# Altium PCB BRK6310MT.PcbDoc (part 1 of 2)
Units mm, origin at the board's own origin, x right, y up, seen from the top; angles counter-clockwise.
Board outline 165 x 90 mm, 4 copper layers (L1-Top, L2-Plane-1, L3-Plane-2, L4-Bottom), stack 1.539 mm thick; 47 components, 158 nets, 545 pads, 116 vias.
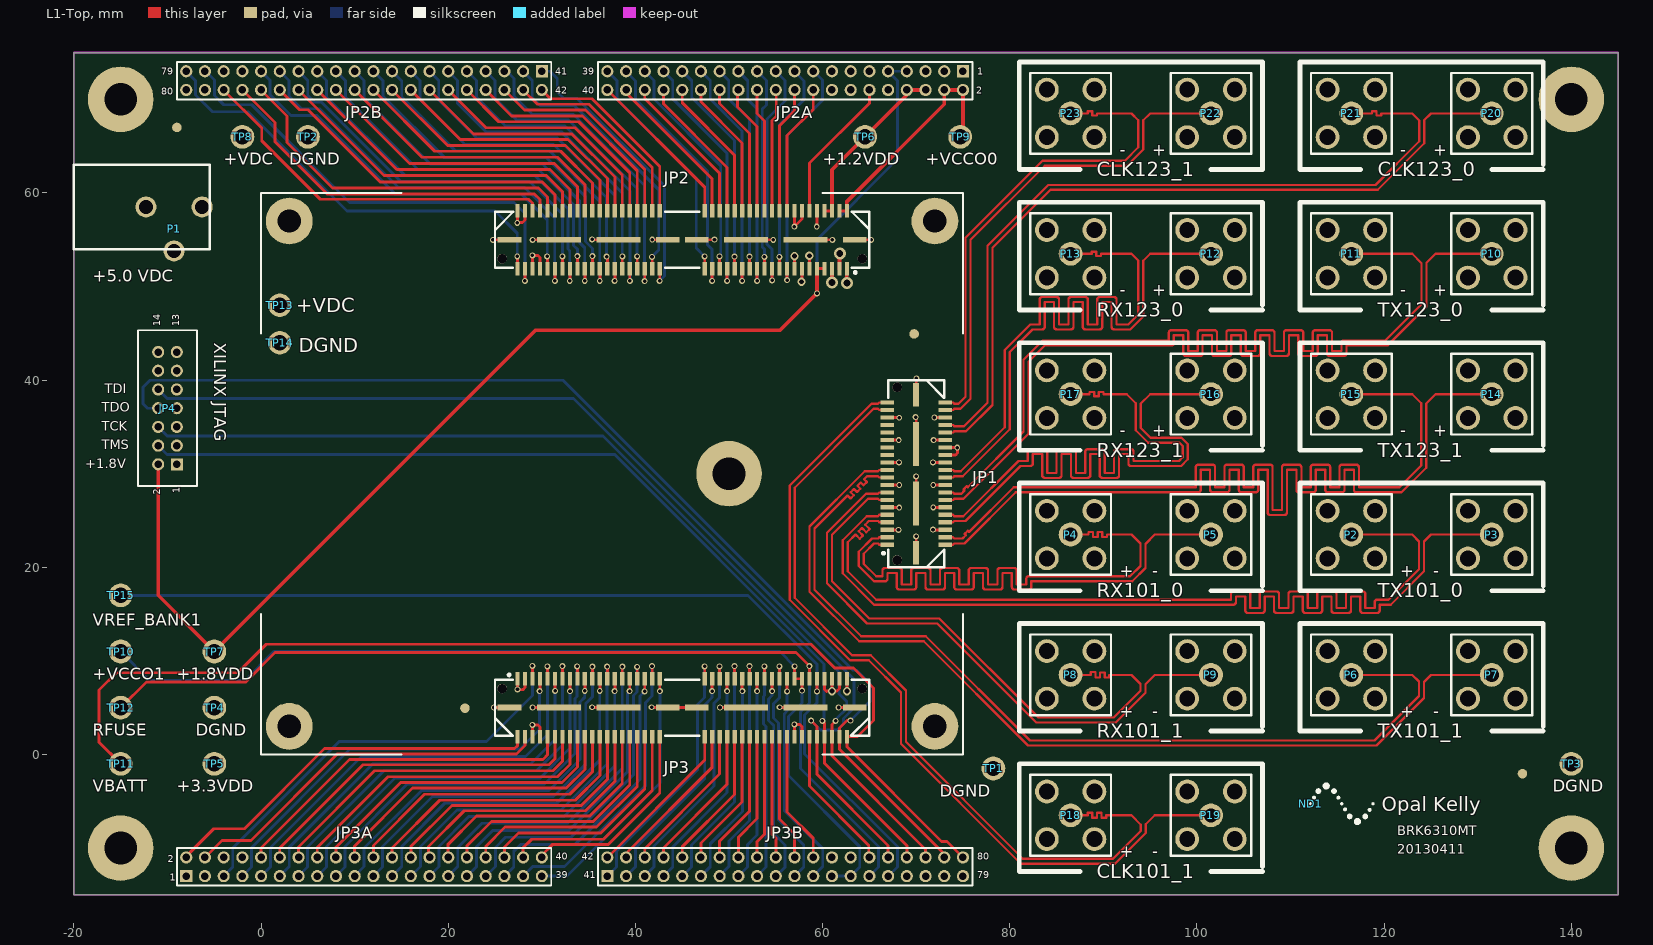
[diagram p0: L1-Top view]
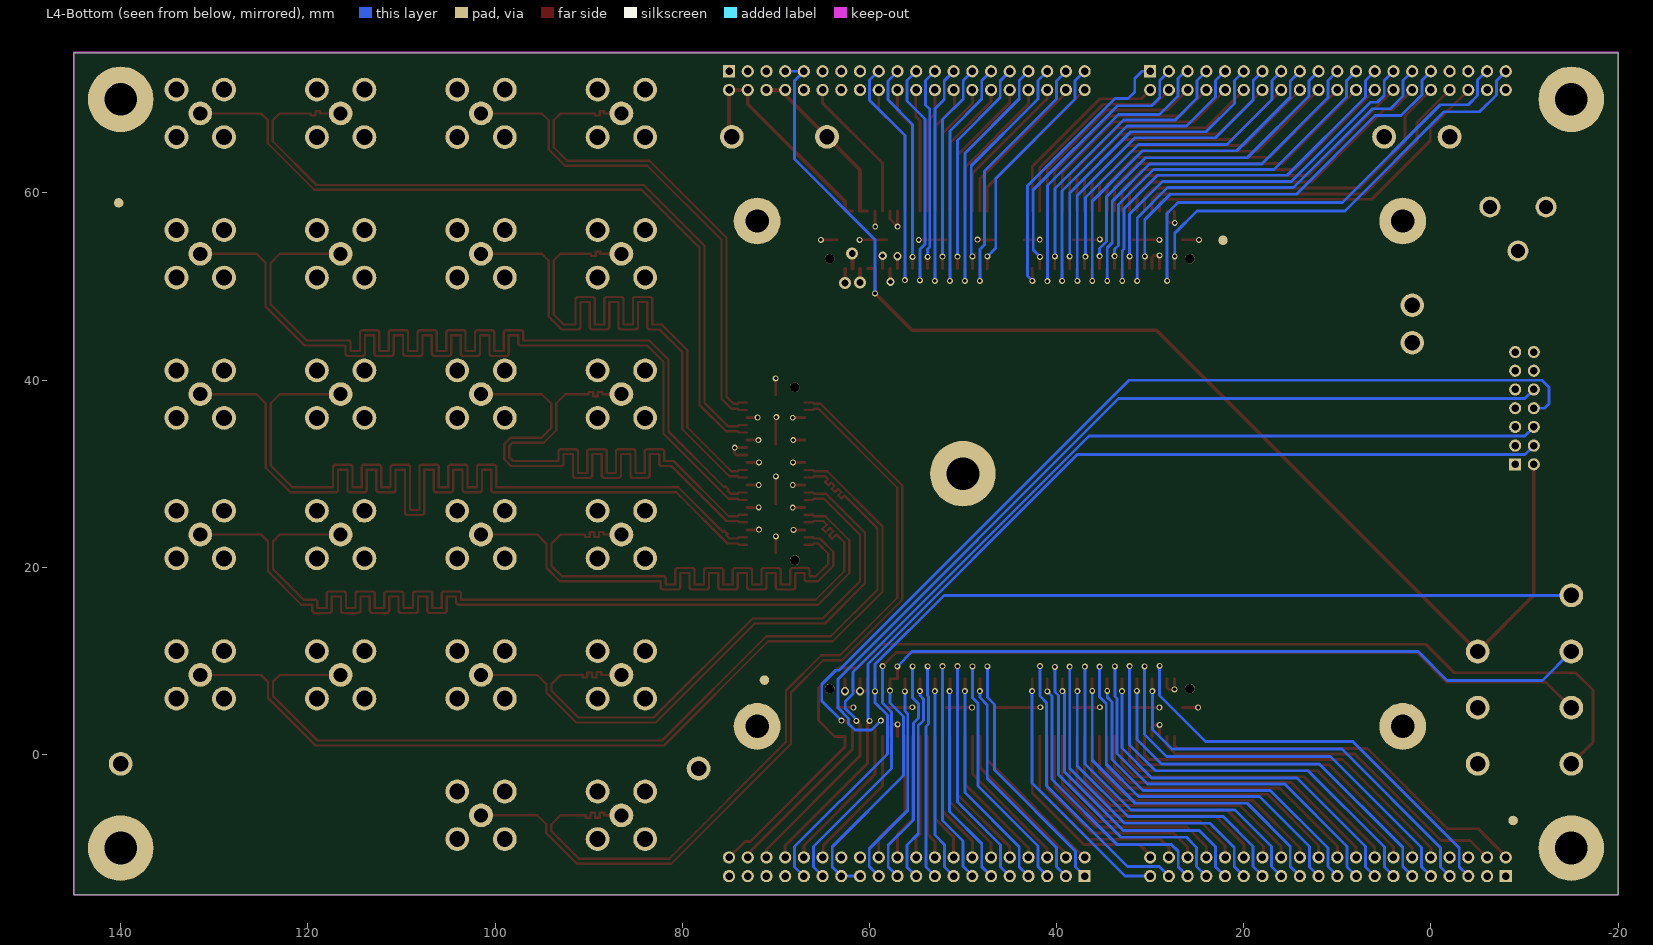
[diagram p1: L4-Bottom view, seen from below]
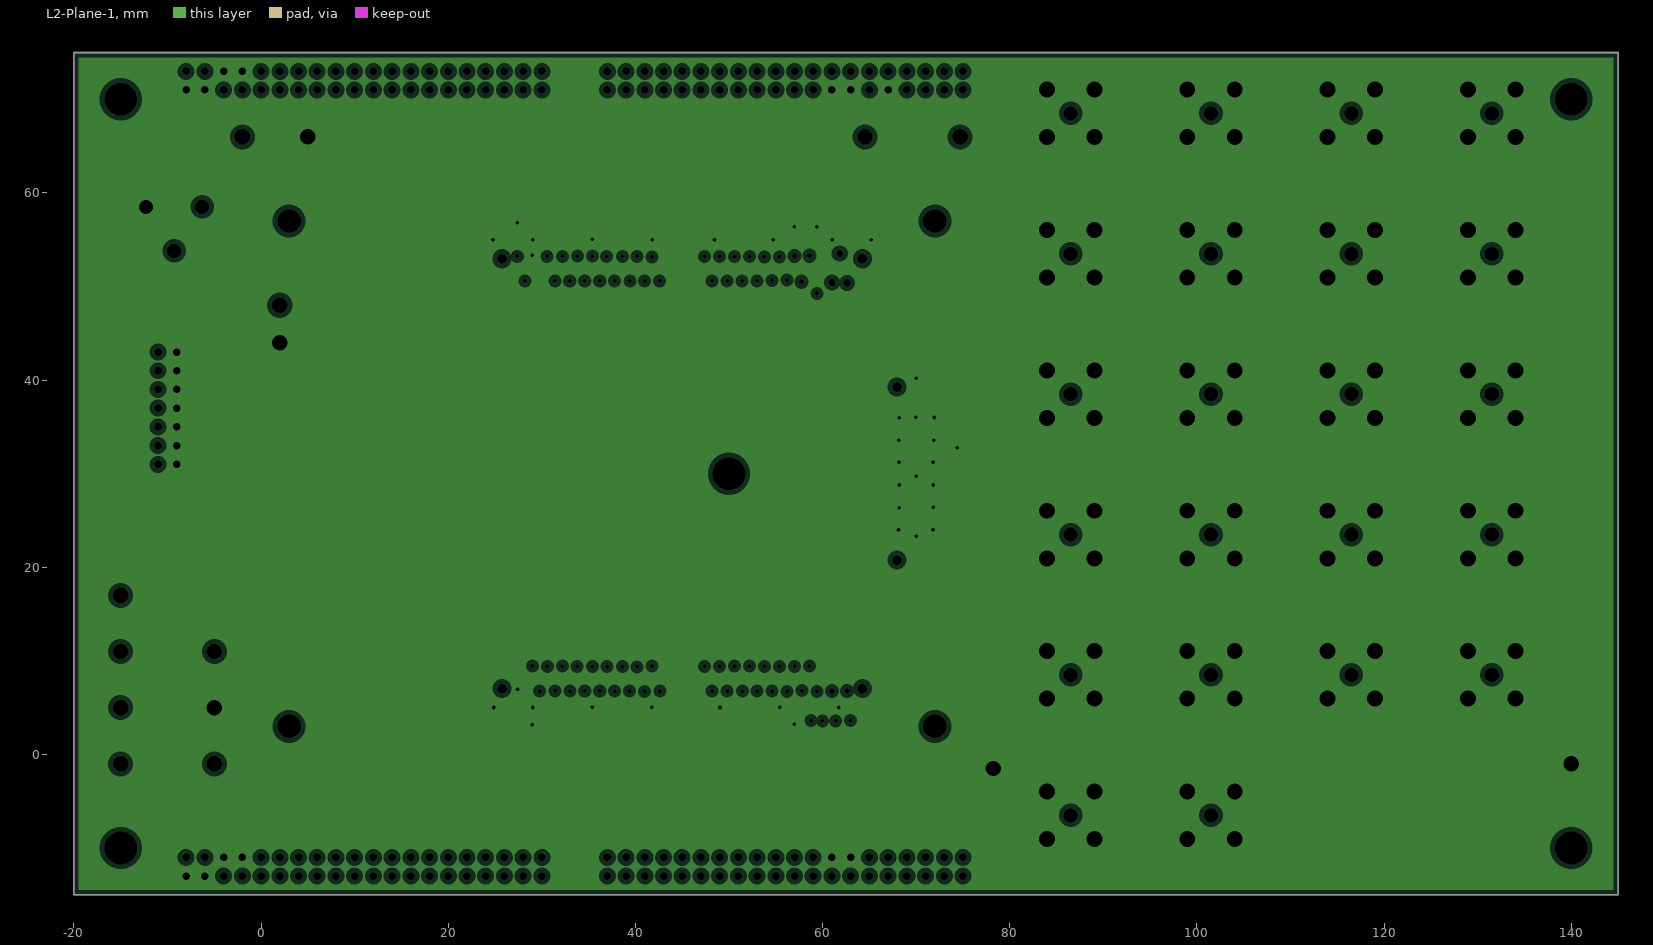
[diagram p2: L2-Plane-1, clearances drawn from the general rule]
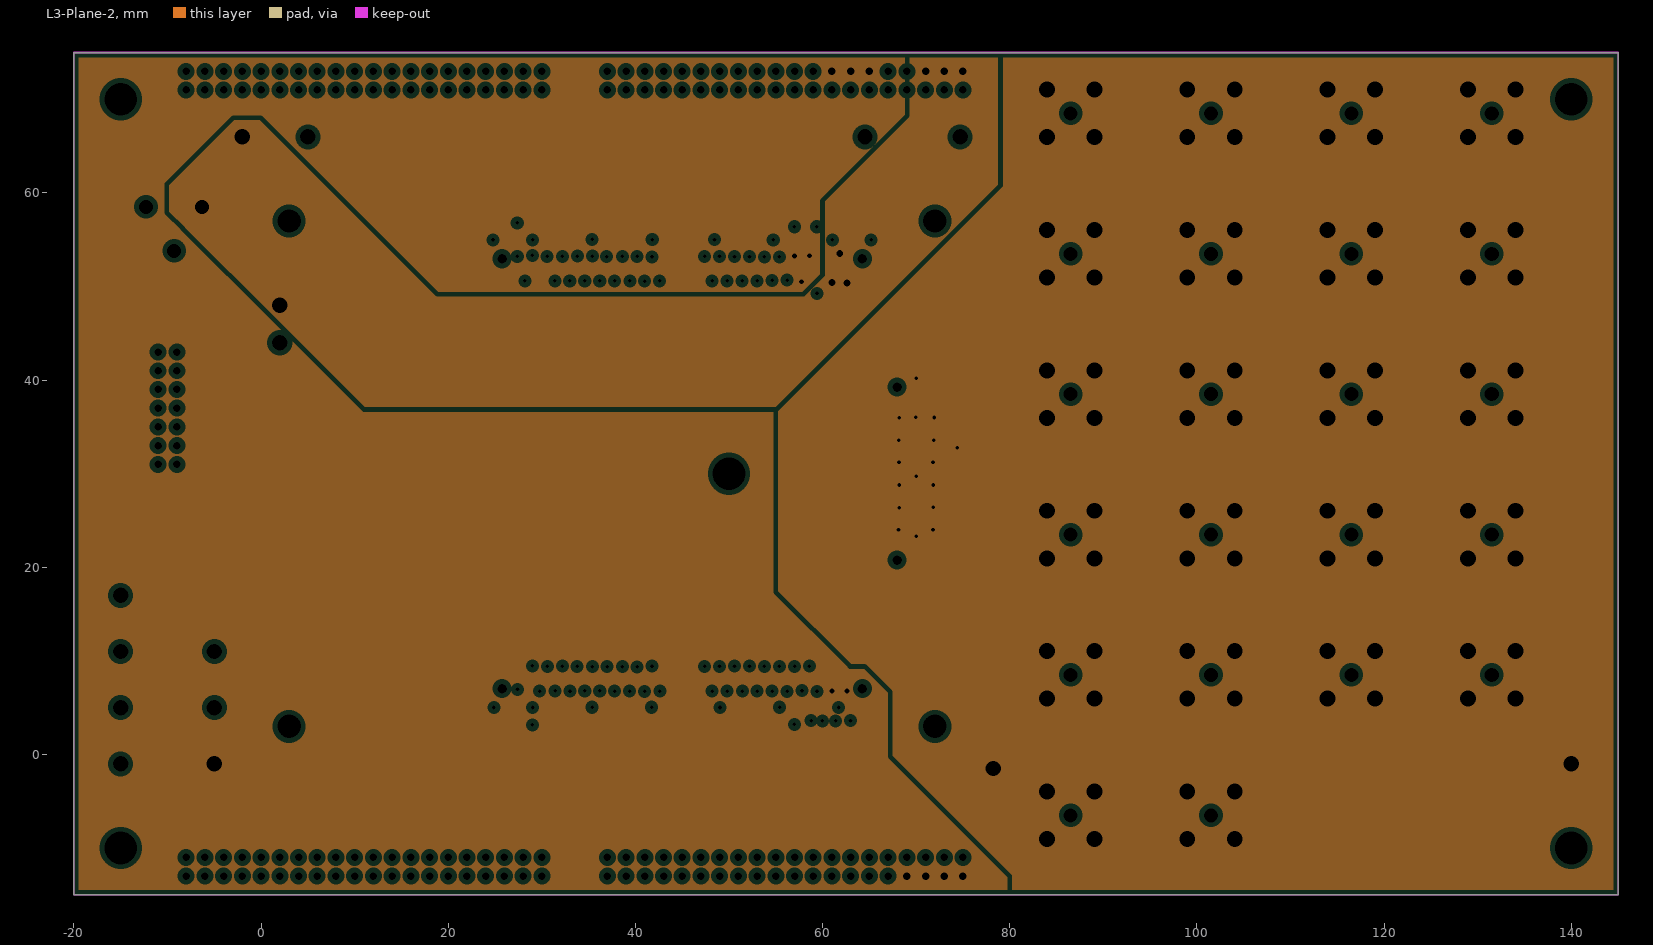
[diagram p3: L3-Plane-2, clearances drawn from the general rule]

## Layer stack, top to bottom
L1-Top: signal copper 0.0533
Dielectric: prepreg 0.1854, FR-4, Dk 4.8
L2-Plane-1: plane copper 0.0356, net DGND
Dielectric: core 0.9906, FR-4, Dk 4.8
L3-Plane-2: plane copper 0.0356, net (Multiple Nets)
Dielectric: prepreg 0.1854, FR-4, Dk 4.8
L4-Bottom: signal copper 0.0533

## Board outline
-20,-15 -20,75 145,75 145,-15

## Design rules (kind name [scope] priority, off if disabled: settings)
Clearance [All] p1: gap=0.152
DiffPairsRouting okxDiffRouting100ohm [All] p1: maxlimit=0.292 minlimit=0.292 mostfreqgap=0.292 maxuncoupledlength=12.7 // Differential pair spacing for all 100ohm diff routes based on Saturn Stackup.
FabricationTestPointUsage TestPointUsage [All] p1: valid=0 allowmultiple=FALSE
FabricationTestpoint Testpoint [All] p1: side=3 testpointundercomponent=TRUE minsize=1.016 maxsize=2.54 preferedsize=1.524 minholesize=0 maxholesize=1.016 preferedholesize=0.813 testpointgrid=0.025 allowsidetop=TRUE allowsidebottom=TRUE usegrid=TRUE gridtolerance=0
HoleSize [All] p1: absolutevalues=TRUE maxlimit=6 minlimit=0.381 maxpercent=80.000 minpercent=20.000
MatchedLengths okMatchedMGTDiffPairs [InNetClass('okMGT')] p1: tolerance=0.152 checknetsindiffpair=TRUE checkdiffpairvsdiffpair=FALSE checkothers=FALSE // Control skew within MGTdiferential pairs.
MatchedLengths okMatchedMGTRefClkDiffPairs [InNetClass('okMGTRefClk')] p2: tolerance=1.676 checknetsindiffpair=TRUE checkdiffpairvsdiffpair=FALSE checkothers=FALSE // Control skew within MGTREFCLKdiferential pairs.
MatchedLengths okMatchedMGTTX [InDifferentialPairClass('okMGTDiffTXMatch')] p3: tolerance=4.699 checknetsindiffpair=TRUE checkdiffpairvsdiffpair=TRUE checkothers=TRUE // MGT TX matched to 31.25ps
MatchedLengths okMatchedMGTRX [InDifferentialPairClass('okMGTDiffRXMatch')] p4: tolerance=4.699 checknetsindiffpair=TRUE checkdiffpairvsdiffpair=TRUE checkothers=TRUE // MGT RX matched to 31.25ps
PlaneClearance [All] p1: clearance=0.508
PlaneConnect [All] p1: planeconnectstyle=Relief reliefexpansion=0.508 reliefentries=4 reliefconductorwidth=0.254 reliefairgap=0.254
PolygonConnect "Via Connect" [IsVia] p1: connectstyle=Direct reliefconductorwidth=0.254 reliefentries=4 polygonreliefangle="90 Angle" airgapwidth=0.254
PolygonConnect [All] p2: connectstyle=Relief reliefconductorwidth=0.254 reliefentries=4 polygonreliefangle="90 Angle" airgapwidth=0.254
RoutingVias [All] p1: holewidth=0.381 width=0.635 viastyle="Through Hole" minholewidth=0.254 minwidth=0.508 maxholewidth=1.27 maxwidth=2.54
SilkscreenOverComponentPads [All] p1: minsilkscreentomaskgap=0.254
SolderMaskExpansion [All] p1: expansion=0.102
Width okxWidthDiff100ohm [(InDifferentialPairClass('All Differential Pairs'))] p1: maxlimit=0.241 minlimit=0.241 preferedwidth=0.241 minimp=50.000000 maximp=50.000000 favimp=50.000000 // 100 ohm differential pair routing based on 4 layer stackup from Saturn
Width okWidth50ohm [All] p2: maxlimit=1.016 minlimit=0.305 preferedwidth=0.305 minimp=50.000000 maximp=50.000000 favimp=50.000000 // 50 ohm SE routing based on 4 layer stackup from Saturn
21 further rules are at their usual default settings.

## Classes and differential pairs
net class okMGT: RX101_0N RX101_0P RX101_1N RX101_1P RX123_0N RX123_0P RX123_1N RX123_1P TX101_0N TX101_0P TX101_1N TX101_1P TX123_0N TX123_0P TX123_1N TX123_1P
differential pair class okMGTDiffPairs: D_CLK101_1 D_CLK123_0 D_CLK123_1 D_RX101_0 D_RX101_1 D_RX123_0 D_RX123_1 D_TX101_0 D_TX101_1 D_TX123_0 D_TX123_1
differential pair class okMGTDiffTXMatch: D_TX101_0 D_TX101_1 D_TX123_0 D_TX123_1
differential pair class okMGTDiffRXMatch: D_RX101_0 D_RX101_1 D_RX123_0 D_RX123_1
net class okMGTRefClk: CLK101_1N CLK101_1P CLK123_0N CLK123_0P CLK123_1N CLK123_1P
differential pair D_TX123_1: +TX123_1P -TX123_1N
differential pair D_TX123_0: +TX123_0P -TX123_0N
differential pair D_RX123_1: +RX123_1P -RX123_1N
differential pair D_RX123_0: +RX123_0P -RX123_0N
differential pair D_CLK123_0: +CLK123_0P -CLK123_0N
differential pair D_TX101_1: +TX101_1P -TX101_1N
differential pair D_TX101_0: +TX101_0P -TX101_0N
differential pair D_RX101_1: +RX101_1P -RX101_1N
differential pair D_RX101_0: +RX101_0P -RX101_0N
differential pair D_CLK123_1: +CLK123_1P -CLK123_1N
differential pair D_CLK101_1: +CLK101_1P -CLK101_1N

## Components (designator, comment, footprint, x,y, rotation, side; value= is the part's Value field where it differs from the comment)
JP1 "QTE-020-01-F-D-A" QTE-020-01-X-D-A 70,30 r90 top locked
JP2 "QTE-040-01-F-D-A" QTE-040-01-X-D-A 45,55 r180 top locked
JP2A "Header 20X2" HDR2X20-2MM 56,72 r180 top
JP2B "Header 20X2" HDR2X20-2MM 11,72 r180 top
JP3 "QTE-040-01-F-D-A" QTE-040-01-X-D-A 45,5 r0 top locked
JP3A "Header 20X2" HDR2X20-2MM 11,-12 r0 top
JP3B "Header 20X2" HDR2X20-2MM 56,-12 r0 top
JP4 "JTAG" XILINX-JTAG -10,37 r90 top
ND1 "OKLOGO" oklogotiny 112.145,-5.268 r0 top
P1 "+5.0 VDC" CUI-PJ102A -20,58.5 r270 top
P2 "TX101_0" SMA 116.5,23.5 r0 top
P3 "TX101_0N" SMA 131.5,23.5 r0 top
P4 "RX101_0" SMA 86.5,23.5 r0 top
P5 "RX101_0N" SMA 101.5,23.5 r0 top
P6 "TX101_1" SMA 116.5,8.5 r0 top
P7 "TX101_1N" SMA 131.5,8.5 r0 top
P8 "RX101_1" SMA 86.5,8.5 r0 top
P9 "RX101_1N" SMA 101.5,8.5 r0 top
P10 "TX123_0P" SMA 131.5,53.5 r0 top
P11 "TX123_0" SMA 116.5,53.5 r0 top
P12 "RX123_0P" SMA 101.5,53.5 r0 top
P13 "RX123_0" SMA 86.5,53.5 r0 top
P14 "TX123_1P" SMA 131.5,38.5 r0 top
P15 "TX123_1" SMA 116.5,38.5 r0 top
P16 "RX123_1P" SMA 101.5,38.5 r0 top
P17 "RX123_1" SMA 86.5,38.5 r0 top
P18 "CLK101_1" SMA 86.5,-6.5 r0 top
P19 "CLK101_1N" SMA 101.5,-6.5 r0 top
P20 "CLK123_0P" SMA 131.5,68.5 r0 top
P21 "CLK123_0" SMA 116.5,68.5 r0 top
P22 "CLK123_1P" SMA 101.5,68.5 r0 top
P23 "CLK123_1" SMA 86.5,68.5 r0 top
TP1 "DGND" TP_MED#1 78.25,-1.5 r0 top
TP2 "DGND" TP_MED#1 5,66 r0 top
TP3 "DGND" TP_MED#1 140,-1 r180 top
TP4 "DGND" TP_MED#1 -5,5 r0 top
TP5 "+3.3VDD" TP_MED#1 -5,-1 r0 top
TP6 "+1.2VDD" TP_MED#2 60,66 r0 top
TP7 "+1.8VDD" TP_MED#1 -5,11 r0 top
TP8 "+VDC" TP_MED#1 -2,66 r0 top
TP9 "+VCCO0" TP_MED#3 75,66 r0 top
TP10 "+VCCO1" TP_MED#4 -15.8,11 r0 top
TP11 "VBATT" TP_MED#1 -15,-1 r0 top
TP12 "RFUSE" TP_MED#1 -15,5 r0 top
TP13 "+VDC" POGO-PR541-1-Press-Ring-Stop#1 2,50 r0 top locked
TP14 "DGND" POGO-PR541-1-Press-Ring-Stop#2 2,45 r0 top locked
TP15 "VREF_BANK1" TP_MED#1 -15,17 r0 top

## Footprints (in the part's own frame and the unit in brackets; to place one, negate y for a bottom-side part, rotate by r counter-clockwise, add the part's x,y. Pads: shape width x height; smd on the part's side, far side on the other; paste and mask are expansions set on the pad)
CUI-PJ102A [mm] "2.1mm/5.5mm DC power jack"
  round 2.25 hole 1.5: 1(0,13.7) 2(0,7.7) 3(4.7,10.7)
  silkscreen extent -4.5,0 4.5,14.5
HDR2X20-2MM [mm] "2mm 2x20 header"
  rect 1.3x1.3 hole 0.8: 1(-19,-1)
  round 1.3 hole 0.8: 2(-19,1) 3(-17,-1) 4(-17,1) 5(-15,-1) 6(-15,1) 7(-13,-1) 8(-13,1) 9(-11,-1) 10(-11,1) 11(-9,-1) 12(-9,1) 13(-7,-1) 14(-7,1) 15(-5,-1) 16(-5,1) 17(-3,-1) 18(-3,1) 19(-1,-1) 20(-1,1) 21(1,-1) 22(1,1) 23(3,-1) 24(3,1) 25(5,-1) 26(5,1) 27(7,-1) 28(7,1) 29(9,-1) 30(9,1) 31(11,-1) 32(11,1) 33(13,-1) 34(13,1) 35(15,-1) 36(15,1) 37(17,-1) 38(17,1) 39(19,-1) 40(19,1)
  silkscreen extent -20,-2 20,2
oklogotiny [mm] "Opal Kelly silkscreen logo (50 mil)."
  silkscreen extent -0.09,-2.1 6.75,2.1
POGO-PR541-1-Press-Ring-Stop#1 [mm] "P2664 Series Receptical Undersized to use press ring as stop"
  round 2.5 hole 1.68: 1(0,-2)
POGO-PR541-1-Press-Ring-Stop#2 [mm] "P2664 Series Receptical Undersized to use press ring as stop"
  round 2.5 hole 1.68: 1(0,-1)
QTE-020-01-X-D-A [mil] "0.80mm, 40 pin Surface Mount connectors with Ground Strip"
  rect 100x25 smd paste+0: 0(-332.5,0) 0(332.5,0)
  rect 185x25 smd paste+0: 0(-125,0) 0(125,0)
  rect 18x57 smd paste+0: 1(-299.25,121.5) 2(-299.25,-121.5) 3(-267.75,121.5) 4(-267.75,-121.5) 5(-236.25,121.5) 6(-236.25,-121.5) 7(-204.75,121.5) 8(-204.75,-121.5) 9(-173.25,121.5) 10(-173.25,-121.5) 11(-141.75,121.5) 12(-141.75,-121.5) 13(-110.25,121.5) 14(-110.25,-121.5) 15(-78.75,121.5) 16(-78.75,-121.5) 17(-47.25,121.5) 18(-47.25,-121.5) 19(-15.75,121.5) 20(-15.75,-121.5) 21(15.75,121.5) 22(15.75,-121.5) 23(47.25,121.5) 24(47.25,-121.5) 25(78.75,121.5) 26(78.75,-121.5) 27(110.25,121.5) 28(110.25,-121.5) 29(141.75,121.5) 30(141.75,-121.5) 31(173.25,121.5) 32(173.25,-121.5) 33(204.75,121.5) 34(204.75,-121.5) 35(236.25,121.5) 36(236.25,-121.5) 37(267.75,121.5) 38(267.75,-121.5) 39(299.25,121.5) 40(299.25,-121.5)
  round 40 hole 40 paste+0: MH(-363.75,80) MH(363.75,80)
  silkscreen extent -394,-118 394,143
QTE-040-01-X-D-A [mil] "0.80mm, 80 pin Surface Mount connectors with Ground Strip"
  rect 100x25 smd paste+0: 0(-726.25,0) 0(-61.25,0) 0(61.25,0) 0(726.25,0)
  rect 185x25 smd paste+0: 0(-518.75,0) 0(-268.75,0) 0(268.75,0) 0(518.75,0)
  rect 18x57 smd paste+0: 1(-693,121.5) 2(-693,-121.5) 3(-661.5,121.5) 4(-661.5,-121.5) 5(-630,121.5) 6(-630,-121.5) 7(-598.5,121.5) 8(-598.5,-121.5) 9(-567,121.5) 10(-567,-121.5) 11(-535.5,121.5) 12(-535.5,-121.5) 13(-504,121.5) 14(-504,-121.5) 15(-472.5,121.5) 16(-472.5,-121.5) 17(-441,121.5) 18(-441,-121.5) 19(-409.5,121.5) 20(-409.5,-121.5) 21(-378,121.5) 22(-378,-121.5) 23(-346.5,121.5) 24(-346.5,-121.5) 25(-315,121.5) 26(-315,-121.5) 27(-283.5,121.5) 28(-283.5,-121.5) 29(-252,121.5) 30(-252,-121.5) 31(-220.5,121.5) 32(-220.5,-121.5) 33(-189,121.5) 34(-189,-121.5) 35(-157.5,121.5) 36(-157.5,-121.5) 37(-126,121.5) 38(-126,-121.5) 39(-94.5,121.5) 40(-94.5,-121.5) 41(94.5,121.5) 42(94.5,-121.5) 43(126,121.5) 44(126,-121.5) 45(157.5,121.5) 46(157.5,-121.5) 47(189,121.5) 48(189,-121.5) 49(220.5,121.5) 50(220.5,-121.5) 51(252,121.5) 52(252,-121.5) 53(283.5,121.5) 54(283.5,-121.5) 55(315,121.5) 56(315,-121.5) 57(346.5,121.5) 58(346.5,-121.5) 59(378,121.5) 60(378,-121.5) 61(409.5,121.5) 62(409.5,-121.5) 63(441,121.5) 64(441,-121.5) 65(472.5,121.5) 66(472.5,-121.5) 67(504,121.5) 68(504,-121.5) 69(535.5,121.5) 70(535.5,-121.5) 71(567,121.5) 72(567,-121.5) 73(598.5,121.5) 74(598.5,-121.5) 75(630,121.5) 76(630,-121.5) 77(661.5,121.5) 78(661.5,-121.5) 79(693,121.5) 80(693,-121.5)
  round 40 hole 40 paste+0: MH(-757.5,80) MH(757.5,80)
  silkscreen extent -788,-118 788,143
SMA [mil] "PCB-mount SMA connector"
  round 100 hole 59: 1(0,0)
  round 100 hole 67: 2(-100,-100) 2(-100,100) 2(100,-100) 2(100,100)
  Top Overlay keep-out lines w10: -170,-170 -170,170 170,170 170,-170 -170,-170
  silkscreen extent -170,-170 170,170
TP_MED#1 [mil] "Testpoint - medium sized"
  round 100 hole 65: 1(0,0)
TP_MED#2 [mil] "Testpoint - medium sized"
  round 100 hole 65: 1(178.43,0)
TP_MED#3 [mil] "Testpoint - medium sized"
  round 100 hole 65: 1(-11.81,0)
TP_MED#4 [mil] "Testpoint - medium sized"
  round 100 hole 65: 1(31.5,0)
XILINX-JTAG [mm] "2mm 2x7 header"
  rect 1.3x1.3 hole 0.8: 1(-6,-1)
  round 1.3 hole 0.8: 2(-6,1) 3(-4,-1) 4(-4,1) 5(-2,-1) 6(-2,1) 7(0,-1) 8(0,1) 9(2,-1) 10(2,1) 11(4,-1) 12(4,1) 13(6,-1) 14(6,1)
  silkscreen extent -8.32,-3.15 8.32,3.15

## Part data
JP1: library part 000973, "0.8mm hi-speed, high-density header (female)"
JP2 JP3: library part 000972, "0.8mm hi-speed, high-density header (female)"
JP2A JP2B JP3A JP3B: "Header, 20-Pin, Dual row"
JP4: library part 000541, "2mm header, shrouded"
ND1: "Opal Kelly PCB Logo"
P1: library part DCPOWER, "DC Power Connector"
P2 P3 P4 P5 P6 P7 P8 P9 P10 P11 P12 P13 P14 P15 P16 P17 P18 P19 P20 P21 P22 P23: library part 000974, "Straight SMA PCB Mount"
TP1 TP2 TP3 TP4 TP5 TP6 TP7 TP8 TP9 TP10 TP11 TP12 TP15: library part TESTPOINT, "Testpoint"
TP13 TP14: library part 000768, "Pogo Pin Socket"

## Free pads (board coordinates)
  round 5 hole 2.5: 0(3,3) 0(3,57) 0(72,3) 0(72,57)
  round 1.016 smd mask+0.508: FD3(-9,67) FD3(21.783,4.942) FD3(69.783,44.942) FD3(134.783,-2.058)
  round 1.016 smd far side mask+0.508: FD3(-8.783,-7.058) FD3(22.217,54.942) FD3(71.217,7.942) FD3(140.217,58.942)
  round 7 hole 3.5: MH(-15,-10) MH(-15,70) MH(50,30) MH(140,-10) MH(140,70)

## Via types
v1: diameter 0.635, hole 0.381, L1-Top to L4-Bottom, tented both sides, 108 vias
v2: diameter 0.889, hole 0.508, L1-Top to L4-Bottom, tented both sides, 5 vias
v3: diameter 1.27, hole 0.711, L1-Top to L4-Bottom, tented both sides, 3 vias

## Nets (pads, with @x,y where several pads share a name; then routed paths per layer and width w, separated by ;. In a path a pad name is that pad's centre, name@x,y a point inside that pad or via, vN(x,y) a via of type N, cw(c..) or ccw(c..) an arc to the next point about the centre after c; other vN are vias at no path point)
+1.2VDD: JP2.6 JP2.8 JP2A.6 JP2A.8 TP6.1 | length 19
  L1-Top w0.305: JP2.8@60.202,58.086 JP2.6@61.002,58.086
  L1-Top w0.381: JP2.6@61.002,58.086 61.002,62.47 TP6.1@64.532,66 69,70.468 JP2A.8@69,71 JP2A.6@71,71
+1.8VDD: JP2.7 JP2.9 JP2A.7 JP2A.9 JP4.2 TP7.1 | length 135.9
  L1-Top w0.305: JP2.9@59.402,51.914 JP2.7@60.202,51.914
  L1-Top w0.381: JP4.2@-11,31 -11,17 TP7.1@-5,11 29.35,45.35 55.489,45.35 v1(59.402,49.263) JP2.9@59.402,51.914
  L4-Bottom w0.305: v1(59.402,49.263) 59.402,55.004 68.011,63.613 68.011,71.989 JP2A.9@67,73 JP2A.7@69,73
+3.3VDD: JP2.11 JP2.13 JP2.15 JP2A.11 JP2A.13 JP2A.15 JP3.73 JP3.75 JP3.77 JP3.79 JP3B.33 JP3B.35 JP3B.37 JP3B.39 TP5.1 | length 10.8
  L1-Top w0.305: v2(57,53.25) 57.001,53.249 JP2.15@57.001,51.914 ; v2(57.75,50.5) 57.802,50.552 JP2.13@57.802,51.914 ; v2(58.588,53.301) 58.602,53.286 JP2.11@58.602,51.914 ; JP3.73@60.202,8.086 60.202,6.957 60.416,6.742 60.442,6.768 v2(61.001,6.768) ; JP3.75@61.002,8.086 61.001,8.085 v2(61.001,6.768) ; JP3.77@61.802,8.086 61.802,7.036 61.534,6.768 v2(61.001,6.768) ; v2(62.601,6.768) 62.601,6.869 62.602,6.871 JP3.79@62.602,8.086
+VCCO0: JP2.2 JP2.4 JP2A.2 JP2A.4 TP9.1 | length 25.1
  L1-Top w0.305: JP2.4@61.802,58.086 JP2.2@62.602,58.086
  L1-Top w0.381: JP2.2@62.602,58.086 62.602,59.086 73,69.484 JP2A.4@73,71 JP2A.2@75,71 75,66.3 TP9.1@74.7,66
+VCCO1: JP3.65 JP3.67 JP3B.25 JP3B.27 TP10.1 | length 104.6
  L1-Top w0.305: v1(57.013,9.409) 57.001,9.398 JP3.65@57.001,8.086 JP3.67@57.802,8.086 v1(57.8,6.819) v1(57.8,6.819)
  L4-Bottom w0.305: TP10.1@-15,11 -11.911,7.911 -1.712,7.911 1.361,10.984 55.438,10.984 v1(57.013,9.409) ; v1(57.8,6.819) 57.8,5.498 56.352,4.05 56.352,-2.249 63.972,-9.869 63.972,-12.028 JP3B.27@63,-13 JP3B.25@61,-13
+VDC: JP2.1 JP2.3 JP2.5 JP2A.1 JP2A.3 JP2A.5 P1.1 TP8.1 TP13.1 | length 4.6
  L1-Top w0.305: v3(61.001,50.43) v3(61.001,50.43) ; v3@61.802,53.492 v3(61.839,53.529) ; v3(62.601,50.38) v3(62.601,50.38)
  L1-Top w0.381: v3(61.001,50.43) JP2.5@61.002,51.914 ; JP2.3@61.802,51.914 v3@61.802,53.492 ; v3(62.601,50.38) JP2.1@62.602,51.914
CLK101_1N: JP1.39 P19.1 | length 88.9
  L1-Top w0.241: JP1.39@66.914,37.601 66.058,37.601 65.925,37.468 65.216,37.468 56.479,28.731 56.479,16.521 62.93,10.07 64.92,10.07 68.367,6.623 68.367,1.137 81.176,-11.673 91.252,-11.673 94.533,-8.391 94.533,-7.467 95.5,-6.5 P19.1@101.5,-6.5
CLK101_1P: JP1.37 P18.1 | length 88.9
  L1-Top w0.241: JP1.37@66.914,36.801 66.058,36.801 65.925,36.934 65.437,36.934 57.013,28.51 57.013,16.742 63.151,10.603 65.141,10.603 68.9,6.844 68.9,1.358 81.397,-11.139 91.031,-11.139 94,-8.17 94,-7.5 93,-6.5 90.306,-6.5 90.306,-6.767 89.811,-6.767 89.811,-6.233 89.315,-6.233 89.315,-6.767 88.82,-6.767 88.82,-6.233 88.325,-6.233 88.325,-6.5 P18.1@86.5,-6.5
CLK123_0N: JP1.34 P21.1 | length 83.9
  L1-Top w0.241: JP1.34@73.086,35.201 73.932,35.201 74.066,35.067 75.108,35.067 77.61,37.569 77.61,54.351 84.12,60.861 119.089,60.861 123.75,65.522 123.75,67.75 123,68.5 119.694,68.5 119.694,68.271 119.198,68.271 119.198,68.729 118.703,68.729 118.703,68.5 P21.1@116.5,68.5
CLK123_0P: JP1.32 P20.1 | length 83.8
  L1-Top w0.241: JP1.32@73.086,34.401 73.932,34.401 74.066,34.534 75.329,34.534 78.143,37.348 78.143,54.13 84.341,60.327 119.31,60.327 124.283,65.301 124.283,67.783 125,68.5 P20.1@131.5,68.5
CLK123_1N: JP1.40 P23.1 | length 53.4
  L1-Top w0.241: JP1.40@73.086,37.601 73.932,37.601 74.066,37.468 74.511,37.468 75.273,38.23 75.273,55.222 83.503,63.452 92.317,63.452 93.739,64.873 93.739,67.761 93,68.5 89.315,68.5 89.315,68.271 88.82,68.271 88.82,68.729 88.325,68.729 88.325,68.5 P23.1@86.5,68.5
CLK123_1P: JP1.38 P22.1 | length 53.3
  L1-Top w0.241: JP1.38@73.086,36.801 73.932,36.801 74.066,36.934 74.732,36.934 75.807,38.009 75.807,55.001 83.724,62.918 92.538,62.918 94.272,64.652 94.272,67.772 95,68.5 P22.1@101.5,68.5
DGND: JP1.0 JP1.5 JP1.6 JP1.11 JP1.12 JP1.17 JP1.18 JP1.23 JP1.24 JP1.26 JP1.28 JP1.29 JP1.30 JP1.35 JP1.36 JP2.0 JP2.10 JP2.14 JP2.16 JP2.73 JP2.75 JP2.78 JP2.80 JP2A.10 JP2A.14 JP2A.16 JP2B.33 JP2B.35 JP2B.38 JP2B.40 JP3.0 JP3.1 JP3.3 JP3.6 JP3.8 JP3.66 JP3.68 JP3A.1 JP3A.3 JP3A.6 JP3A.8 JP3B.26 JP3B.28 JP4.1 JP4.3 JP4.5 JP4.7 JP4.9 JP4.11 JP4.13 P1.2 P2.2 P3.2 P4.2 P5.2 P6.2 P7.2 P8.2 P9.2 P10.2 P11.2 P12.2 P13.2 P14.2 P15.2 P16.2 P17.2 P18.2 P19.2 P20.2 P21.2 P22.2 P23.2 TP1.1 TP2.1 TP3.1 TP4.1 TP14.1 | length 87
  L1-Top w0.305: v1(24.778,54.993) 24.785,55 JP2.0@26.553,55 ; v1(24.882,5.015) 24.897,5 JP3.0@26.553,5 ; JP3.1@27.398,8.086 v1(27.396,6.946) v1(27.396,6.946) 27.422,6.92 27.955,6.92 28.198,7.163 JP3.3@28.198,8.086 ; JP2.80@27.398,58.086 27.398,56.833 27.931,56.833 28.198,57.099 JP2.78@28.198,58.086 ; JP3.6@28.998,1.914 28.998,3.16 29.582,3.16 29.798,2.944 JP3.8@29.798,1.914 ; JP2.75@28.998,51.914 28.998,53.325 v1(28.997,53.326) 29.581,53.326 29.798,53.109 JP2.73@29.798,51.914 ; v1(29.02,54.993) 29.026,55 JP2.0@31.824,55 ; v1(29.022,5.015) 29.037,5 JP3.0@31.824,5 ; v1(35.37,55.044) 35.414,55 JP2.0@38.174,55 ; v1(35.372,5.041) 35.413,5 JP3.0@38.174,5 ; v1(41.722,5.041) 41.763,5 JP3.0@43.444,5 JP3.0@46.556,5 ; v1(41.796,55.019) 41.815,55 JP2.0@43.444,55 ; JP2.0@46.556,55 48.432,55 v1(48.451,55.019) ; v1(49.037,5.015) 49.052,5 JP3.0@51.826,5 ; JP2.0@51.826,55 54.718,55 v1(54.725,54.993) ; v1(55.413,5.041) 55.453,5 JP3.0@58.176,5 ; JP3.66@57.001,1.914 57.001,3.198 57.013,3.186 57.572,3.186 57.802,2.956 JP3.68@57.802,1.914 ; JP2.16@57.001,58.086 57.001,56.407 57.802,57.207 JP2.14@57.802,58.086 ; JP2.0@58.176,55 61.043,55 v1(61.049,54.993) ; v1(59.373,56.39) 59.402,56.419 JP2.10@59.402,58.086 ; v1(61.712,5.015) 61.727,5 JP3.0@63.447,5 ; JP2.0@63.447,55 65.183,55 v1(65.189,54.993) ; JP1.5@66.914,23.999 68.102,23.999 v1(68.113,23.989) ; JP1.11@66.914,26.4 68.166,26.4 v1(68.189,26.377) ; JP1.17@66.914,28.8 68.179,28.8 v1(68.189,28.79) ; JP1.23@66.914,31.2 68.161,31.2 v1(68.163,31.203) ; JP1.29@66.914,33.6 68.128,33.6 v1(68.138,33.59) ; JP1.35@66.914,36.001 68.166,36.001 v1(68.189,35.978) ; v1(69.941,36.054) 70,35.995 JP1.0@70,33.175 ; v1(69.992,23.303) 70,23.295 JP1.0@70,21.555 ; v1(69.992,29.704) 70,29.696 JP1.0@70,26.825 ; JP1.0@70,38.446 70,40.177 v1(70.018,40.194) ; v1(71.796,24.014) 71.811,23.999 JP1.6@73.086,23.999 ; v1(71.796,31.203) 71.798,31.2 JP1.24@73.086,31.2 ; v1(71.821,26.402) 71.823,26.4 JP1.12@73.086,26.4 ; v1(71.821,28.79) 71.831,28.8 JP1.18@73.086,28.8 ; v1(71.872,33.59) 71.882,33.6 JP1.30@73.086,33.6 ; v1(71.948,36.003) 71.95,36.001 JP1.36@73.086,36.001 ; JP1.26@73.086,32 74.219,32 74.412,32.193 74.412,32.8 JP1.28@73.086,32.8
  other v1: 28.997,3.161 56.987,3.212 74.386,32.777 56.985,56.39 27.371,56.806
JP2_12: JP2.12 JP2A.12 | length 15.6
  L1-Top w0.305: JP2.12@58.602,58.086 58.602,63.188 65,69.587 JP2A.12@65,71
JP2_17: JP2.17 JP2A.17 | length 25.6
  L1-Top w0.305: v1(56.2,50.684) v1(56.2,50.684) JP2.17@56.201,51.914
  L4-Bottom w0.305: v1(56.2,50.684) 56.2,66.128 59.985,69.912 59.985,72.071 59.056,73 JP2A.17@59,73
JP2_18: JP2.18 JP2A.18 | length 14.1
  L1-Top w0.305: JP2.18@56.201,58.086 56.201,66.122 59,68.921 JP2A.18@59,71
JP2_19: JP2.19 JP2A.19 | length 22.6
  L1-Top w0.305: v1(55.387,53.174) 55.401,53.159 JP2.19@55.401,51.914
  L4-Bottom w0.305: v1(55.387,53.174) 55.387,67.321 58.029,69.963 58.029,71.971 JP2A.19@57,73
JP2_20: JP2.20 JP2A.20 | length 13.6
  L1-Top w0.305: JP2.20@55.401,58.086 55.401,67.176 57,68.775 JP2A.20@57,71
JP2_21: JP2.21 JP2A.21 | length 25
  L1-Top w0.305: v1(54.6,50.659) v1(54.6,50.659) JP2.21@54.601,51.914
  L4-Bottom w0.305: v1(54.6,50.659) 54.6,53.986 54.066,54.52 54.066,67.906 55.997,69.836 55.997,72.003 JP2A.21@55,73
JP2_22: JP2.22 JP2A.22 | length 13.1
  L1-Top w0.305: JP2.22@54.601,58.086 54.601,67.722 55.055,68.176 55.055,70.945 JP2A.22@55,71
JP2_23: JP2.23 JP2A.23 | length 21.8
  L1-Top w0.305: v1(53.787,53.174) 53.801,53.159 JP2.23@53.801,51.914
  L4-Bottom w0.305: JP2A.23@53,73 53.99,72.01 53.99,69.404 53.558,68.972 53.558,54.215 53.787,53.986 v1(53.787,53.174)
JP2_24: JP2.24 JP2A.24 | length 13.2
  L1-Top w0.305: JP2A.24@53,71 53,68.489 53.801,67.688 JP2.24@53.801,58.086
JP2_25: JP2.25 JP2A.25 | length 24.5
  L1-Top w0.305: v1(53,50.608) v1(53,50.608) JP2.25@53.001,51.914
  L4-Bottom w0.305: JP2A.25@51,73 52.009,71.991 52.009,69.988 53,68.998 v1(53,50.608)
JP2_26: JP2.26 JP2A.26 | length 13.8
  L1-Top w0.305: JP2A.26@51,71 50.915,70.915 50.915,69.178 53.001,67.091 JP2.26@53.001,58.086
JP2_27: JP2.27 JP2A.27 | length 22.4
  L1-Top w0.305: v1(52.187,53.199) 52.201,53.185 JP2.27@52.201,51.914
  L4-Bottom w0.305: JP2A.27@49,73 49.977,72.023 49.977,70.039 52.187,67.829 v1(52.187,53.199)
JP2_28: JP2.28 JP2A.28 | length 14.2
  L1-Top w0.305: JP2A.28@49,71 49,69.543 52.201,66.342 JP2.28@52.201,58.086
JP2_29: JP2.29 JP2A.29 | length 25.5
  L1-Top w0.305: v1(51.399,50.608) v1(51.399,50.608) JP2.29@51.401,51.914
  L4-Bottom w0.305: JP2A.29@47,73 47.996,72.004 47.996,70.039 51.399,66.636 v1(51.399,50.608)
JP2_30: JP2.30 JP2A.30 | length 14.7
  L1-Top w0.305: JP2A.30@47,71 47,69.74 51.401,65.339 JP2.30@51.401,58.086
JP2_31: JP2.31 JP2A.31 | length 23.4
  L1-Top w0.305: v1(50.587,53.199) 50.601,53.185 JP2.31@50.601,51.914
  L4-Bottom w0.305: JP2A.31@45,73 46.015,71.985 46.015,70.192 50.587,65.62 v1(50.587,53.199)
JP2_32: JP2.32 JP2A.32 | length 15.2
  L1-Top w0.305: JP2A.32@45,71 45,69.631 50.601,64.031 JP2.32@50.601,58.086
JP2_33: JP2.33 JP2A.33 | length 26.5
  L1-Top w0.305: v1(49.799,50.608) v1(49.799,50.608) JP2.33@49.801,51.914
  L4-Bottom w0.305: JP2A.33@43,73 43.983,72.017 43.983,70.065 49.799,64.248 v1(49.799,50.608)
JP2_34: JP2.34 JP2A.34 | length 15.7
  L1-Top w0.305: JP2A.34@43,71 42.99,70.99 42.99,69.533 49.801,62.723 JP2.34@49.801,58.086
JP2_35: JP2.35 JP2A.35 | length 24.5
  L1-Top w0.305: v1(48.986,53.224) 49,53.21 JP2.35@49,51.914
  L4-Bottom w0.305: JP2A.35@41,73 41.976,72.024 41.976,70.039 49.113,62.902 49.113,53.351 v1(48.986,53.224)
JP2_36: JP2.36 JP2A.36 | length 16.2
  L1-Top w0.305: JP2A.36@41,71 41,70.101 49,62.1 JP2.36@49,58.086
JP2_37: JP2.37 JP2A.37 | length 27.5
  L1-Top w0.305: v1(48.199,50.608) v1(48.199,50.608) JP2.37@48.2,51.914
  L4-Bottom w0.305: JP2A.37@39,73 39,72.964 40.02,71.944 40.02,70.039 47.716,62.343 47.716,54.469 48.199,53.986 v1(48.199,50.608)
JP2_38: JP2.38 JP2A.38 | length 16.7
  L1-Top w0.305: JP2A.38@39,71 39,70.704 48.2,61.503 JP2.38@48.2,58.086
JP2_39: JP2.39 JP2A.39 | length 25.4
  L1-Top w0.305: v1(47.386,53.224) 47.4,53.21 JP2.39@47.4,51.914
  L4-Bottom w0.305: JP2A.39@37,73 38.014,71.986 38.014,70.039 46.497,61.556 46.497,54.113 v1(47.386,53.224)
JP2_40: JP2.40 JP2A.40 | length 17.2
  L1-Top w0.305: JP2A.40@37,71 47.4,60.6 JP2.40@47.4,58.086
JP2_41: JP2.41 JP2B.1 | length 30.7
  L1-Top w0.305: v1(42.586,50.608) 42.6,50.622 JP2.41@42.6,51.914
  L4-Bottom w0.305: JP2B.1@30,73 30.862,73 31.638,72.224 31.638,70.801 32.349,70.09 33.772,70.09 43.094,60.768 43.094,51.116 v1(42.586,50.608)
JP2_42: JP2.42 JP2B.2 | length 20.7
  L1-Top w0.305: JP2B.2@30,71 30.935,70.065 35.372,70.065 42.6,62.837 JP2.42@42.6,58.086
JP2_43: JP2.43 JP2B.3 | length 29.5
  L1-Top w0.305: v1(41.773,53.174) 41.8,53.147 JP2.43@41.8,51.914
  L4-Bottom w0.305: JP2B.3@28,73 28.971,72.029 28.971,70.192 29.847,69.315 33.505,69.315 42.484,60.336 42.484,53.885 v1(41.773,53.174)
JP2_44: JP2.44 JP2B.4 | length 21.9
  L1-Top w0.305: JP2B.4@28,71 29.52,69.48 35.042,69.48 41.8,62.723 JP2.44@41.8,58.086
JP2_45: JP2.45 JP2B.5 | length 32.7
  L1-Top w0.305: v1(40.985,50.583) 40.999,50.597 JP2.45@40.999,51.914
  L4-Bottom w0.305: JP2B.5@26,73 26.264,73 27.041,72.224 27.041,70.344 28.997,68.388 33.391,68.388 40.985,60.794 v1(40.985,50.583)
JP2_46: JP2.46 JP2B.6 | length 22.9
  L1-Top w0.305: JP2B.6@26,71 28.155,68.845 34.661,68.845 40.999,62.507 JP2.46@40.999,58.086
JP2_47: JP2.47 JP2B.7 | length 31
  L1-Top w0.305: v1(40.173,53.224) 40.199,53.198 JP2.47@40.199,51.914
  L4-Bottom w0.305: JP2B.7@24,73 24.983,72.017 24.983,70.141 27.32,67.804 32.857,67.804 40.173,60.489 v1(40.173,53.224)
JP2_48: JP2.48 JP2B.8 | length 24.1
  L1-Top w0.305: JP2B.8@24,71 26.764,68.236 34.331,68.236 40.199,62.367 JP2.48@40.199,58.086
JP2_49: JP2.49 JP2B.9 | length 34.6
  L1-Top w0.305: JP2.49@39.399,51.914 39.399,50.619 v1(39.411,50.608)
  L4-Bottom w0.305: JP2B.9@22,73 23.002,71.998 23.002,70.268 26.126,67.144 32.476,67.144 39.411,60.209 v1(39.411,50.608)
JP2_50: JP2.50 JP2B.10 | length 25.1
  L1-Top w0.305: JP2B.10@22,71 25.399,67.601 33.95,67.601 39.399,62.151 JP2.50@39.399,58.086
JP2_51: JP2.51 JP2B.11 | length 33.5
  L1-Top w0.305: v1(38.598,53.224) 38.599,53.223 JP2.51@38.599,51.914
  L4-Bottom w0.305: JP2B.11@20,73 20.996,72.004 20.996,69.557 24.018,66.534 32.07,66.534 38.598,60.006 v1(38.598,53.224)
JP2_52: JP2.52 JP2B.12 | length 26.2
  L1-Top w0.305: JP2B.12@20,71 24.034,66.966 33.543,66.966 38.599,61.91 JP2.52@38.599,58.086
JP2_53: JP2.53 JP2B.13 | length 36.9
  L1-Top w0.305: v1(37.785,50.608) 37.799,50.622 JP2.53@37.799,51.914
  L4-Bottom w0.305: JP2B.13@18,73 18.989,72.011 18.989,69.938 23.028,65.899 31.613,65.899 37.785,59.727 v1(37.785,50.608)
JP2_54: JP2.54 JP2B.14 | length 27.3
  L1-Top w0.305: JP2B.14@18,71 22.695,66.305 33.188,66.305 37.799,61.694 JP2.54@37.799,58.086
JP2_55: JP2.55 JP2B.15 | length 35.3
  L1-Top w0.305: v1(36.921,53.199) 36.999,53.121 JP2.55@36.999,51.914
  L4-Bottom w0.305: JP2B.15@16,73 16.982,72.018 16.982,69.988 21.783,65.188 31.257,65.188 36.921,59.524 v1(36.921,53.199)
JP2_56: JP2.56 JP2B.16 | length 28.4
  L1-Top w0.305: JP2B.16@16,71 21.279,65.721 32.807,65.721 36.999,61.529 JP2.56@36.999,58.086
JP2_57: JP2.57 JP2B.17 | length 38.8
  L1-Top w0.305: v1(36.185,50.608) 36.199,50.622 JP2.57@36.199,51.914
  L4-Bottom w0.305: JP2B.17@14,73 15.027,71.973 15.027,70.217 20.742,64.502 30.8,64.502 36.185,59.117 v1(36.185,50.608)
JP2_58: JP2.58 JP2B.18 | length 29.5
  L1-Top w0.305: JP2B.18@14,71 19.939,65.061 32.527,65.061 36.199,61.389 JP2.58@36.199,58.086
JP2_59: JP2.59 JP2B.19 | length 37.1
  L1-Top w0.305: v1(35.397,53.25) 35.399,53.248 JP2.59@35.399,51.914
  L4-Bottom w0.305: JP2B.19@12,73 13.02,71.98 13.02,70.369 19.624,63.765 30.495,63.765 34.661,59.6 34.661,54.799 35.397,54.063 v1(35.397,53.25)
JP2_60: JP2.60 JP2B.20 | length 30.5
  L1-Top w0.305: JP2B.20@12,71 18.549,64.451 32.019,64.451 35.399,61.072 JP2.60@35.399,58.086
JP2_61: JP2.61 JP2B.21 | length 40.9
  L1-Top w0.305: v1(34.585,50.608) 34.599,50.622 JP2.61@34.599,51.914
  L4-Bottom w0.305: JP2B.21@10,73 10.988,72.012 10.988,70.192 18.075,63.105 30.063,63.105 34.051,59.117 34.051,54.672 34.585,54.139 v1(34.585,50.608)
JP2_62: JP2.62 JP2B.22 | length 31.6
  L1-Top w0.305: JP2B.22@10,71 17.184,63.816 31.664,63.816 34.599,60.881 JP2.62@34.599,58.086
JP2_63: JP2.63 JP2B.23 | length 39.3
  L1-Top w0.305: v1(33.797,53.25) 33.799,53.248 JP2.63@33.799,51.914
  L4-Bottom w0.305: JP2B.23@8,73 9.007,71.993 9.007,70.268 16.754,62.521 29.632,62.521 33.391,58.762 33.391,54.393 33.797,53.986 v1(33.797,53.25)
JP2_64: JP2.64 JP2B.24 | length 32.7
  L1-Top w0.305: JP2B.24@8,71 15.87,63.13 31.333,63.13 33.799,60.665 JP2.64@33.799,58.086
JP2_65: JP2.65 JP2B.25 | length 43
  L1-Top w0.305: v1(32.984,50.608) 32.998,50.622 JP2.65@32.998,51.914
  L4-Bottom w0.305: JP2B.25@6,73 6.975,72.025 6.975,70.268 15.357,61.886 29.2,61.886 32.781,58.304 32.781,54.012 32.984,53.809 v1(32.984,50.608)
JP2_66: JP2.66 JP2B.26 | length 33.7
  L1-Top w0.305: JP2B.26@6,71 14.505,62.495 30.876,62.495 32.998,60.373 JP2.66@32.998,58.086
JP2_67: JP2.67 JP2B.27 | length 41.3
  L1-Top w0.305: v1(32.197,53.224) 32.198,53.223 JP2.67@32.198,51.914
  L4-Bottom w0.305: JP2B.27@4,73 4.994,72.006 4.994,70.42 5.73,69.684 6.467,69.684 14.925,61.225 28.692,61.225 32.197,57.72 v1(32.197,53.224)
JP2_68: JP2.68 JP2B.28 | length 34.7
  L1-Top w0.305: JP2B.28@4,71 13.14,61.86 30.47,61.86 32.198,60.132 JP2.68@32.198,58.086
JP2_69: JP2.69 JP2B.29 | length 44.9
  L1-Top w0.305: v1(31.384,50.608) 31.398,50.622 JP2.69@31.398,51.914
  L4-Bottom w0.305: JP2B.29@2,73 2.987,72.013 2.987,70.344 4.333,68.998 6.238,68.998 14.671,60.565 28.158,60.565 31.384,57.339 v1(31.384,50.608)
JP2_70: JP2.70 JP2B.30 | length 35.8
  L1-Top w0.305: JP2B.30@2,71 4.104,68.896 5.019,68.896 12.741,61.175 30.038,61.175 31.398,59.814 JP2.70@31.398,58.086
JP2_71: JP2.71 JP2B.31 | length 43.3
  L1-Top w0.305: v1(30.571,53.224) 30.598,53.198 JP2.71@30.598,51.914
  L4-Bottom w0.305: JP2B.31@0,73 0.955,72.045 0.955,70.496 3.19,68.261 5.959,68.261 14.366,59.854 27.854,59.854 30.571,57.136 v1(30.571,53.224)
JP2_72: JP2.72 JP2B.32 | length 38.5
  L1-Top w0.305: JP2B.32@0,71 2.784,68.216 2.784,65.391 7.635,60.54 29.632,60.54 30.598,59.573 JP2.72@30.598,58.086
JP2_74: JP2.74 JP2B.34 | length 39
  L1-Top w0.305: JP2B.34@-2,71 1.488,67.512 1.488,65.467 7.051,59.905 29.174,59.905 29.798,59.281 JP2.74@29.798,58.086
JP2_76: JP2.76 JP2B.36 | length 39.6
  L1-Top w0.305: JP2B.36@-4,71 0.066,66.934 0.066,65.569 6.314,59.32 28.59,59.32 28.998,58.913 JP2.76@28.998,58.086
JP2_77: JP2.77 JP2B.37 | length 49.9
  L1-Top w0.305: v1(28.184,50.608) 28.198,50.622 JP2.77@28.198,51.914
  L4-Bottom w0.305: JP2B.37@-6,73 -5.917,73 -4.989,72.071 -4.989,70.42 -3.998,69.43 -1.001,69.43 9.464,58.965 27.015,58.965 28.184,57.796 v1(28.184,50.608)
JP2_79: JP2.79 JP2B.39 | length 47.2
  L1-Top w0.305: v1(27.371,53.224) 27.398,53.198 JP2.79@27.398,51.914
  L4-Bottom w0.305: JP2B.39@-8,73 -6.995,71.995 -6.995,70.471 -5.192,68.668 -1.407,68.668 9.185,58.076 24.983,58.076 27.371,55.688 v1(27.371,53.224)
JP3_2: JP3.2 JP3A.2 | length 41.4
  L1-Top w0.305: JP3A.2@-8,-11 -8,-10.874 -5.065,-7.939 -1.788,-7.939 6.772,0.621 27.092,0.621 27.398,0.927 JP3.2@27.398,1.914
JP3_4: JP3.4 JP3A.4 | length 40.1
  L1-Top w0.305: JP3A.4@-6,-11 -4.183,-9.183 -1.077,-9.183 8.143,0.037 27.295,0.037 28.198,0.94 JP3.4@28.198,1.914
JP3_5: JP3.5 JP3A.5 | length 46.7
  L1-Top w0.305: v1(28.997,9.46) 28.998,9.459 JP3.5@28.998,8.086
  L4-Bottom w0.305: JP3A.5@-4,-13 -3.033,-12.033 -3.033,-9.996 8.346,1.383 24.094,1.383 28.997,6.285 v1(28.997,9.46)
JP3_7: JP3.7 JP3A.7 | length 44.9
  L1-Top w0.305: v1(29.759,6.768) 29.798,6.807 JP3.7@29.798,8.086
  L4-Bottom w0.305: JP3A.7@-2,-13 -1.026,-12.026 -1.026,-9.971 9.515,0.57 27.65,0.57 29.759,2.678 v1(29.759,6.768)
JP3_9: JP3.9 JP3A.9 | length 46.7
  L1-Top w0.305: v1(30.597,9.409) 30.598,9.408 JP3.9@30.598,8.086
  L4-Bottom w0.305: JP3A.9@0,-13 1.006,-11.994 1.006,-9.945 10.734,-0.217 28.26,-0.217 30.597,2.12 v1(30.597,9.409)
JP3_10: JP3.10 JP3A.10 | length 37.7
  L1-Top w0.305: JP3A.10@0,-11 0,-9.986 9.464,-0.522 30.114,-0.522 30.598,-0.038 JP3.10@30.598,1.914
JP3_11: JP3.11 JP3A.11 | length 43.2
  L1-Top w0.305: JP3.11@31.398,8.086 31.398,6.804 v1(31.41,6.793)
  L4-Bottom w0.305: JP3A.11@2,-13 3.012,-11.988 3.012,-9.92 11.928,-1.005 28.793,-1.005 31.41,1.612 v1(31.41,6.793)
JP3_12: JP3.12 JP3A.12 | length 36.7
  L1-Top w0.305: JP3A.12@2,-11 2,-9.993 10.886,-1.106 30.749,-1.106 31.398,-0.457 JP3.12@31.398,1.914
JP3_13: JP3.13 JP3A.13 | length 45
  L1-Top w0.305: v1(32.197,9.435) 32.198,9.433 JP3.13@32.198,8.086
  L4-Bottom w0.305: JP3A.13@4,-13 4.968,-12.032 4.968,-9.895 13.122,-1.741 29.428,-1.741 32.197,1.027 v1(32.197,9.435)
JP3_14: JP3.14 JP3A.14 | length 35.8
  L1-Top w0.305: JP3A.14@4,-11 4,-9.872 12.131,-1.741 31.181,-1.741 32.198,-0.724 JP3.14@32.198,1.914
JP3_15: JP3.15 JP3A.15 | length 41.4
  L1-Top w0.305: JP3.15@32.998,8.086 32.998,6.779 v1(33.01,6.768)
  L4-Bottom w0.305: JP3A.15@6,-13 6.975,-12.025 6.975,-9.844 14.315,-2.503 29.835,-2.503 33.01,0.672 v1(33.01,6.768)
JP3_16: JP3.16 JP3A.16 | length 34.7
  L1-Top w0.305: JP3A.16@6,-11 6,-9.93 13.553,-2.376 31.689,-2.376 32.998,-1.067 JP3.16@32.998,1.914
JP3_17: JP3.17 JP3A.17 | length 43
  L1-Top w0.305: v1(33.772,9.409) 33.799,9.383 JP3.17@33.799,8.086
  L4-Bottom w0.305: JP3A.17@8,-13 8.956,-12.044 8.956,-9.818 15.611,-3.164 30.292,-3.164 33.543,0.088 33.543,5.98 33.772,6.209 v1(33.772,9.409)
JP3_18: JP3.18 JP3A.18 | length 33.7
  L1-Top w0.305: JP3A.18@8,-11 8,-9.911 14.925,-2.986 32.146,-2.986 33.799,-1.333 JP3.18@33.799,1.914
JP3_19: JP3.19 JP3A.19 | length 39.3
  L1-Top w0.305: v1(34.585,6.793) 34.599,6.807 JP3.19@34.599,8.086
  L4-Bottom w0.305: JP3A.19@10,-13 11.013,-11.987 11.013,-9.996 17.16,-3.849 30.775,-3.849 34.077,-0.547 34.077,5.599 34.585,6.107 v1(34.585,6.793)
JP3_20: JP3.20 JP3A.20 | length 32.7
  L1-Top w0.305: JP3A.20@10,-11 10,-9.765 16.17,-3.595 32.603,-3.595 34.599,-1.6 JP3.20@34.599,1.914
JP3_21: JP3.21 JP3A.21 | length 40.9
  L1-Top w0.305: v1(35.397,9.384) 35.399,9.383 JP3.21@35.399,8.086
  L4-Bottom w0.305: JP3A.21@12,-13 12.969,-12.031 12.969,-9.844 18.329,-4.484 31.257,-4.484 34.686,-1.055 34.686,5.447 35.397,6.158 v1(35.397,9.384)
JP3_22: JP3.22 JP3A.22 | length 31.7
  L1-Top w0.305: JP3A.22@12,-11 12,-9.721 17.465,-4.256 32.984,-4.256 35.399,-1.841 JP3.22@35.399,1.914
JP3_23: JP3.23 JP3A.23 | length 37.3
  L1-Top w0.305: v1(36.185,6.793) 36.199,6.807 JP3.23@36.199,8.086
  L4-Bottom w0.305: JP3A.23@14,-13 15.027,-11.973 15.027,-9.818 19.624,-5.221 31.587,-5.221 36.185,-0.624 v1(36.185,6.793)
